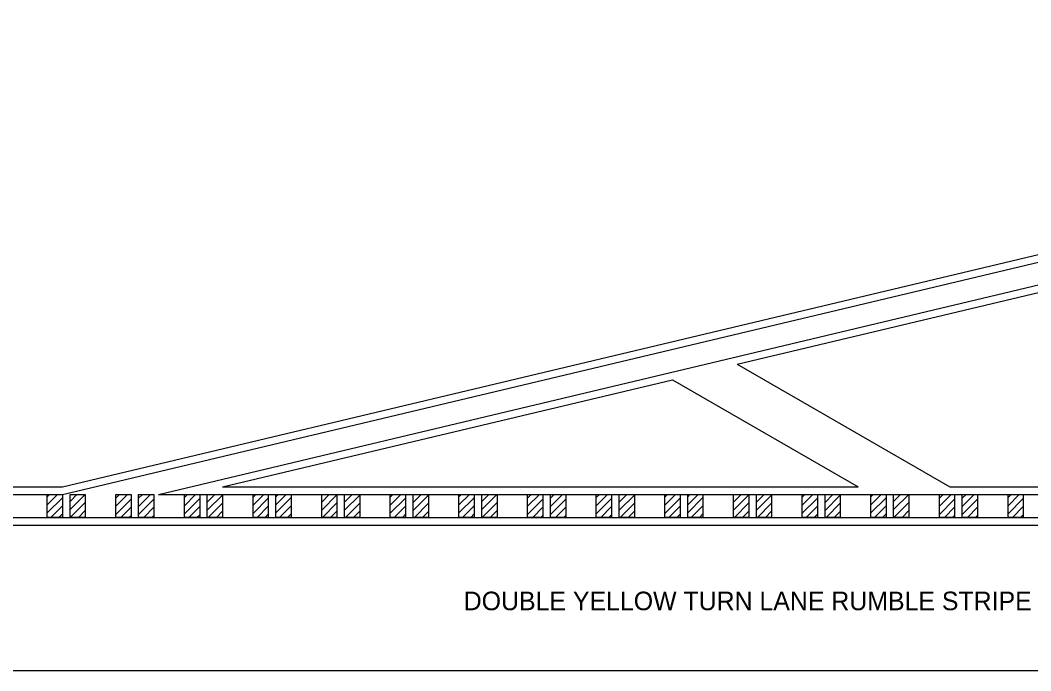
# Model space of a CAD drawing. Extents: x 49976.2 to 50021, y 49987.6 to 50011.4.
# Drawn here: x 50005.455 to 50009.802, y 49987.799 to 49990.599 of the extents above; entities that cross this region are included whole.
import ezdxf

# ---------------------------------------------------------------- set-up
doc = ezdxf.new("R2010")
doc.units = 0
doc.layers.add('Level 1', color=7, linetype='Continuous')
doc.layers.add('Level 2', color=7, linetype='Continuous')

msp = doc.modelspace()

# ---------------------------------------------------------------- linework, layer by layer
at = {"layer": 'Level 1'}
for p, q in [((50005.6367, 49988.5903), (50011.2798, 49989.9353)), ((50005.6367, 49988.5575), (50011.2872, 49989.9043)), ((50006.0496, 49988.5575), (50011.2798, 49989.8041)), ((50008.5395, 49989.1181), (50010.281, 49989.5332)), ((50008.5395, 49989.1181), (50009.4538, 49988.5903)), ((50006.3248, 49988.5903), (50008.2609, 49989.0517)), ((50008.2609, 49989.0517), (50009.0602, 49988.5903)), ((50002.5024, 49988.5903), (50005.6367, 49988.5903)), ((50002.5024, 49988.5575), (50005.6367, 49988.5575)), ((50005.499, 49988.5903), (50005.6367, 49988.5903)), ((50005.5711, 49988.4591), (50005.5711, 49988.5575)), ((50005.5711, 49988.5575), (50005.6367, 49988.5575)), ((50005.5711, 49988.5127), (50005.6158, 49988.5575)), ((50005.5711, 49988.5475), (50005.581, 49988.5575)), ((50005.6367, 49988.5575), (50005.6367, 49988.4591)), ((50005.6695, 49988.4591), (50005.6695, 49988.5575)), ((50005.6695, 49988.5575), (50005.7351, 49988.5575)), ((50005.6695, 49988.4926), (50005.7343, 49988.5575)), ((50005.6695, 49988.5274), (50005.6995, 49988.5575)), ((50005.7351, 49988.5575), (50005.7351, 49988.4591)), ((50005.8663, 49988.4591), (50005.8663, 49988.5575)), ((50005.8663, 49988.5575), (50005.9319, 49988.5575)), ((50005.8663, 49988.5067), (50005.9171, 49988.5575)), ((50005.8663, 49988.5415), (50005.8823, 49988.5575)), ((50005.9319, 49988.5575), (50005.9319, 49988.4591)), ((50005.9647, 49988.4591), (50005.9647, 49988.5575)), ((50005.9647, 49988.5575), (50006.0303, 49988.5575)), ((50005.9647, 49988.5064), (50006.0158, 49988.5575)), ((50005.9647, 49988.5411), (50005.9811, 49988.5575)), ((50006.0303, 49988.5575), (50006.0303, 49988.4591)), ((50006.0496, 49988.5575), (50013.5099, 49988.5575)), ((50006.1615, 49988.4591), (50006.1615, 49988.5575)), ((50006.1615, 49988.5575), (50006.2272, 49988.5575)), ((50006.1615, 49988.5093), (50006.2097, 49988.5575)), ((50006.1615, 49988.5441), (50006.1749, 49988.5575)), ((50006.2272, 49988.5575), (50006.2272, 49988.4591)), ((50006.26, 49988.4591), (50006.26, 49988.5575)), ((50006.26, 49988.5575), (50006.3256, 49988.5575)), ((50006.26, 49988.5244), (50006.2931, 49988.5575)), ((50006.26, 49988.4896), (50006.3256, 49988.5552)), ((50006.3248, 49988.5903), (50009.0602, 49988.5903)), ((50006.3256, 49988.5575), (50006.3256, 49988.4591)), ((50006.4568, 49988.4591), (50006.4568, 49988.5575)), ((50006.4568, 49988.5575), (50006.5224, 49988.5575)), ((50006.4568, 49988.5113), (50006.503, 49988.5575)), ((50006.4568, 49988.5461), (50006.4682, 49988.5575)), ((50006.5224, 49988.5575), (50006.5224, 49988.4591)), ((50006.5552, 49988.4591), (50006.5552, 49988.5575)), ((50006.5552, 49988.5575), (50006.6208, 49988.5575)), ((50006.5552, 49988.5132), (50006.5995, 49988.5575)), ((50006.5552, 49988.548), (50006.5647, 49988.5575)), ((50006.6208, 49988.5575), (50006.6208, 49988.4591)), ((50006.752, 49988.4591), (50006.752, 49988.5575)), ((50006.752, 49988.5575), (50006.8176, 49988.5575)), ((50006.752, 49988.525), (50006.7845, 49988.5575)), ((50006.752, 49988.4902), (50006.8176, 49988.5558)), ((50006.8176, 49988.5575), (50006.8176, 49988.4591)), ((50006.8504, 49988.4591), (50006.8504, 49988.5575)), ((50006.8504, 49988.5575), (50006.9161, 49988.5575)), ((50006.8504, 49988.5244), (50006.8835, 49988.5575)), ((50006.8504, 49988.4896), (50006.9161, 49988.5553)), ((50006.9161, 49988.5575), (50006.9161, 49988.4591)), ((50007.0473, 49988.4591), (50007.0473, 49988.5575)), ((50007.0473, 49988.5575), (50007.1129, 49988.5575)), ((50007.0473, 49988.5116), (50007.0932, 49988.5575)), ((50007.0473, 49988.5464), (50007.0584, 49988.5575)), ((50007.1129, 49988.5575), (50007.1129, 49988.4591)), ((50007.1457, 49988.4591), (50007.1457, 49988.5575)), ((50007.1457, 49988.5575), (50007.2113, 49988.5575)), ((50007.1457, 49988.5236), (50007.1796, 49988.5575)), ((50007.1457, 49988.4888), (50007.2113, 49988.5544)), ((50007.2113, 49988.5575), (50007.2113, 49988.4591)), ((50007.3425, 49988.4591), (50007.3425, 49988.5575)), ((50007.3425, 49988.5575), (50007.4081, 49988.5575)), ((50007.3425, 49988.5127), (50007.3873, 49988.5575)), ((50007.3425, 49988.5475), (50007.3525, 49988.5575)), ((50007.4081, 49988.5575), (50007.4081, 49988.4591)), ((50007.4409, 49988.4591), (50007.4409, 49988.5575)), ((50007.4409, 49988.5575), (50007.5065, 49988.5575)), ((50007.4409, 49988.4926), (50007.5058, 49988.5575)), ((50007.4409, 49988.5274), (50007.471, 49988.5575)), ((50007.5065, 49988.5575), (50007.5065, 49988.4591)), ((50007.6378, 49988.4591), (50007.6378, 49988.5575)), ((50007.6378, 49988.5575), (50007.7034, 49988.5575)), ((50007.6378, 49988.5067), (50007.6885, 49988.5575)), ((50007.6378, 49988.5415), (50007.6538, 49988.5575)), ((50007.7034, 49988.5575), (50007.7034, 49988.4591)), ((50007.7362, 49988.4591), (50007.7362, 49988.5575)), ((50007.7362, 49988.5575), (50007.8018, 49988.5575)), ((50007.7362, 49988.5064), (50007.7873, 49988.5575)), ((50007.7362, 49988.5411), (50007.7525, 49988.5575)), ((50007.8018, 49988.5575), (50007.8018, 49988.4591)), ((50007.933, 49988.4591), (50007.933, 49988.5575)), ((50007.933, 49988.5575), (50007.9986, 49988.5575)), ((50007.933, 49988.5093), (50007.9812, 49988.5575)), ((50007.933, 49988.5441), (50007.9464, 49988.5575)), ((50007.9986, 49988.5575), (50007.9986, 49988.4591)), ((50008.0314, 49988.4591), (50008.0314, 49988.5575)), ((50008.0314, 49988.5575), (50008.097, 49988.5575)), ((50008.0314, 49988.5244), (50008.0645, 49988.5575)), ((50008.0314, 49988.4896), (50008.097, 49988.5552)), ((50008.097, 49988.5575), (50008.097, 49988.4591)), ((50008.2283, 49988.4591), (50008.2283, 49988.5575)), ((50008.2283, 49988.5575), (50008.2939, 49988.5575)), ((50008.2283, 49988.5113), (50008.2744, 49988.5575)), ((50008.2283, 49988.5461), (50008.2397, 49988.5575)), ((50008.2939, 49988.5575), (50008.2939, 49988.4591)), ((50008.3267, 49988.4591), (50008.3267, 49988.5575)), ((50008.3267, 49988.5575), (50008.3923, 49988.5575)), ((50008.3267, 49988.5132), (50008.371, 49988.5575)), ((50008.3267, 49988.548), (50008.3362, 49988.5575)), ((50008.3923, 49988.5575), (50008.3923, 49988.4591)), ((50008.5235, 49988.4591), (50008.5235, 49988.5575)), ((50008.5235, 49988.5575), (50008.5891, 49988.5575)), ((50008.5235, 49988.525), (50008.556, 49988.5575)), ((50008.5235, 49988.4902), (50008.5891, 49988.5558)), ((50008.5891, 49988.5575), (50008.5891, 49988.4591)), ((50008.6219, 49988.4591), (50008.6219, 49988.5575)), ((50008.6219, 49988.5575), (50008.6875, 49988.5575)), ((50008.6219, 49988.5244), (50008.655, 49988.5575)), ((50008.6219, 49988.4896), (50008.6875, 49988.5553)), ((50008.6875, 49988.5575), (50008.6875, 49988.4591)), ((50008.8187, 49988.4591), (50008.8187, 49988.5575)), ((50008.8187, 49988.5575), (50008.8844, 49988.5575)), ((50008.8187, 49988.5116), (50008.8647, 49988.5575)), ((50008.8187, 49988.5464), (50008.8299, 49988.5575)), ((50008.8844, 49988.5575), (50008.8844, 49988.4591)), ((50008.9172, 49988.4591), (50008.9172, 49988.5575)), ((50008.9172, 49988.5575), (50008.9828, 49988.5575)), ((50008.9172, 49988.5236), (50008.9511, 49988.5575)), ((50008.9172, 49988.4888), (50008.9828, 49988.5544)), ((50008.9828, 49988.5575), (50008.9828, 49988.4591)), ((50009.114, 49988.4591), (50009.114, 49988.5575)), ((50009.114, 49988.5575), (50009.1796, 49988.5575)), ((50009.114, 49988.5127), (50009.1587, 49988.5575)), ((50009.114, 49988.5475), (50009.1239, 49988.5575)), ((50009.1796, 49988.5575), (50009.1796, 49988.4591)), ((50009.2124, 49988.4591), (50009.2124, 49988.5575)), ((50009.2124, 49988.5575), (50009.278, 49988.5575)), ((50009.2124, 49988.4926), (50009.2773, 49988.5575)), ((50009.2124, 49988.5274), (50009.2425, 49988.5575)), ((50009.278, 49988.5575), (50009.278, 49988.4591)), ((50009.4092, 49988.4591), (50009.4092, 49988.5575)), ((50009.4092, 49988.5575), (50009.4748, 49988.5575)), ((50009.4092, 49988.5067), (50009.46, 49988.5575)), ((50009.4092, 49988.5415), (50009.4252, 49988.5575)), ((50009.4538, 49988.5903), (50011.9142, 49988.5903)), ((50009.4748, 49988.5575), (50009.4748, 49988.4591)), ((50009.5077, 49988.4591), (50009.5077, 49988.5575)), ((50009.5077, 49988.5575), (50009.5733, 49988.5575)), ((50009.5077, 49988.5064), (50009.5588, 49988.5575)), ((50009.5077, 49988.5411), (50009.524, 49988.5575)), ((50009.5733, 49988.5575), (50009.5733, 49988.4591)), ((50009.7045, 49988.4591), (50009.7045, 49988.5575)), ((50009.7045, 49988.5575), (50009.7701, 49988.5575)), ((50009.7045, 49988.5093), (50009.7527, 49988.5575)), ((50009.7045, 49988.5441), (50009.7179, 49988.5575)), ((50009.7701, 49988.5575), (50009.7701, 49988.4591)), ((50005.5711, 49988.478), (50005.6367, 49988.5436)), ((50005.6707, 49988.4591), (50005.7351, 49988.5234)), ((50005.8663, 49988.4719), (50005.9319, 49988.5375)), ((50005.9647, 49988.4716), (50006.0303, 49988.5372)), ((50006.1615, 49988.4745), (50006.2272, 49988.5401)), ((50006.2642, 49988.4591), (50006.3256, 49988.5204)), ((50006.4568, 49988.4765), (50006.5224, 49988.5421)), ((50006.5552, 49988.4784), (50006.6208, 49988.544)), ((50006.7557, 49988.4591), (50006.8176, 49988.521)), ((50006.8547, 49988.4591), (50006.9161, 49988.5205)), ((50007.0473, 49988.4768), (50007.1129, 49988.5424)), ((50007.1508, 49988.4591), (50007.2113, 49988.5196)), ((50007.3425, 49988.478), (50007.4081, 49988.5436)), ((50007.4422, 49988.4591), (50007.5065, 49988.5234)), ((50007.6378, 49988.4719), (50007.7034, 49988.5375)), ((50007.7362, 49988.4716), (50007.8018, 49988.5372)), ((50007.933, 49988.4745), (50007.9986, 49988.5401)), ((50008.0357, 49988.4591), (50008.097, 49988.5204)), ((50008.2283, 49988.4765), (50008.2939, 49988.5421)), ((50008.3267, 49988.4784), (50008.3923, 49988.544)), ((50008.5271, 49988.4591), (50008.5891, 49988.521)), ((50008.6261, 49988.4591), (50008.6875, 49988.5205)), ((50008.8187, 49988.4768), (50008.8844, 49988.5424)), ((50008.9223, 49988.4591), (50008.9828, 49988.5196)), ((50009.114, 49988.478), (50009.1796, 49988.5436)), ((50009.2137, 49988.4591), (50009.278, 49988.5234)), ((50009.4092, 49988.4719), (50009.4748, 49988.5375)), ((50009.5077, 49988.4716), (50009.5733, 49988.5372)), ((50009.7045, 49988.4745), (50009.7701, 49988.5401)), ((50005.587, 49988.4591), (50005.6367, 49988.5088)), ((50005.6218, 49988.4591), (50005.6367, 49988.474)), ((50005.7055, 49988.4591), (50005.7351, 49988.4886)), ((50005.8883, 49988.4591), (50005.9319, 49988.5027)), ((50005.923, 49988.4591), (50005.9319, 49988.4679)), ((50005.987, 49988.4591), (50006.0303, 49988.5024)), ((50006.0218, 49988.4591), (50006.0303, 49988.4676)), ((50006.1809, 49988.4591), (50006.2272, 49988.5053)), ((50006.2157, 49988.4591), (50006.2272, 49988.4705)), ((50006.299, 49988.4591), (50006.3256, 49988.4856)), ((50006.4742, 49988.4591), (50006.5224, 49988.5073)), ((50006.5089, 49988.4591), (50006.5224, 49988.4725)), ((50006.5707, 49988.4591), (50006.6208, 49988.5092)), ((50006.6055, 49988.4591), (50006.6208, 49988.4744)), ((50006.7905, 49988.4591), (50006.8176, 49988.4862)), ((50006.8895, 49988.4591), (50006.9161, 49988.4857)), ((50007.0644, 49988.4591), (50007.1129, 49988.5076)), ((50007.0992, 49988.4591), (50007.1129, 49988.4728)), ((50007.1856, 49988.4591), (50007.2113, 49988.4848)), ((50007.3584, 49988.4591), (50007.4081, 49988.5088)), ((50007.3932, 49988.4591), (50007.4081, 49988.474)), ((50007.477, 49988.4591), (50007.5065, 49988.4886)), ((50007.6597, 49988.4591), (50007.7034, 49988.5027)), ((50007.6945, 49988.4591), (50007.7034, 49988.4679)), ((50007.7585, 49988.4591), (50007.8018, 49988.5024)), ((50007.7933, 49988.4591), (50007.8018, 49988.4676)), ((50007.9524, 49988.4591), (50007.9986, 49988.5053)), ((50007.9872, 49988.4591), (50007.9986, 49988.4705)), ((50008.0705, 49988.4591), (50008.097, 49988.4856)), ((50008.2456, 49988.4591), (50008.2939, 49988.5073)), ((50008.2804, 49988.4591), (50008.2939, 49988.4725)), ((50008.3421, 49988.4591), (50008.3923, 49988.5092)), ((50008.3769, 49988.4591), (50008.3923, 49988.4744)), ((50008.5619, 49988.4591), (50008.5891, 49988.4862)), ((50008.6609, 49988.4591), (50008.6875, 49988.4857)), ((50008.8358, 49988.4591), (50008.8844, 49988.5076)), ((50008.8706, 49988.4591), (50008.8844, 49988.4728)), ((50008.9571, 49988.4591), (50008.9828, 49988.4848)), ((50009.1299, 49988.4591), (50009.1796, 49988.5088)), ((50009.1647, 49988.4591), (50009.1796, 49988.474)), ((50009.2484, 49988.4591), (50009.278, 49988.4886)), ((50009.4312, 49988.4591), (50009.4748, 49988.5027)), ((50009.466, 49988.4591), (50009.4748, 49988.4679)), ((50009.53, 49988.4591), (50009.5733, 49988.5024)), ((50009.5648, 49988.4591), (50009.5733, 49988.4676)), ((50009.7238, 49988.4591), (50009.7701, 49988.5053)), ((50009.7586, 49988.4591), (50009.7701, 49988.4705)), ((50002.5024, 49988.4591), (50013.5099, 49988.4591)), ((50002.5024, 49988.4263), (50005.6367, 49988.4263)), ((50005.6367, 49988.4591), (50005.5711, 49988.4591)), ((50005.6367, 49988.4263), (50013.5099, 49988.4263)), ((50005.7351, 49988.4591), (50005.6695, 49988.4591)), ((50005.9319, 49988.4591), (50005.8663, 49988.4591)), ((50006.0303, 49988.4591), (50005.9647, 49988.4591)), ((50006.2272, 49988.4591), (50006.1615, 49988.4591)), ((50006.3256, 49988.4591), (50006.26, 49988.4591)), ((50006.5224, 49988.4591), (50006.4568, 49988.4591)), ((50006.6208, 49988.4591), (50006.5552, 49988.4591)), ((50006.8176, 49988.4591), (50006.752, 49988.4591)), ((50006.9161, 49988.4591), (50006.8504, 49988.4591)), ((50007.1129, 49988.4591), (50007.0473, 49988.4591)), ((50007.2113, 49988.4591), (50007.1457, 49988.4591)), ((50007.4081, 49988.4591), (50007.3425, 49988.4591)), ((50007.5065, 49988.4591), (50007.4409, 49988.4591)), ((50007.7034, 49988.4591), (50007.6378, 49988.4591)), ((50007.8018, 49988.4591), (50007.7362, 49988.4591)), ((50007.9986, 49988.4591), (50007.933, 49988.4591)), ((50008.097, 49988.4591), (50008.0314, 49988.4591)), ((50008.2939, 49988.4591), (50008.2283, 49988.4591)), ((50008.3923, 49988.4591), (50008.3267, 49988.4591)), ((50008.5891, 49988.4591), (50008.5235, 49988.4591)), ((50008.6875, 49988.4591), (50008.6219, 49988.4591)), ((50008.8844, 49988.4591), (50008.8187, 49988.4591)), ((50008.9828, 49988.4591), (50008.9172, 49988.4591)), ((50009.1796, 49988.4591), (50009.114, 49988.4591)), ((50009.278, 49988.4591), (50009.2124, 49988.4591)), ((50009.4748, 49988.4591), (50009.4092, 49988.4591)), ((50009.5733, 49988.4591), (50009.5077, 49988.4591)), ((50009.7701, 49988.4591), (50009.7045, 49988.4591))]:
    msp.add_line(p, q, dxfattribs=at)
msp.add_lwpolyline([(49999.3835, 49998.9992), (50016.7501, 49998.9992), (50016.7501, 49987.7988), (49999.3835, 49987.7988)], close=True, dxfattribs=at)

# ---------------------------------------------------------------- texts
at = {"layer": 'Level 2'}
msp.add_text('DOUBLE YELLOW TURN LANE RUMBLE STRIPE', height=0.08, dxfattribs=at).set_placement((50007.3631, 49988.0595))

doc.saveas('drawing.dxf')
